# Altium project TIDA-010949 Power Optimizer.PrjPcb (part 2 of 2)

## Sheet TIDA-010949 Power Optimizer_Hardware.SchDoc
size 431 x 279 mm; Date: Not shown in title block; ApprovedBy: Not shown in title block; CheckedBy: Not shown in title block; Author: Not shown in title block; CompanyName: Not shown in title block; Engineer: Not shown in title block; Organization: Not shown in title block; Address1: Not shown in title block; Address2: Not shown in title block; Address3: Not shown in title block; Address4: Not shown in title block; DocumentNumber: 3; Revision: Use project parameter SCH_Rev; SheetNumber: 6; SheetTotal: 8; PageSetup: Record=PageOptions¦CenterHorizontal=True¦CenterVertical=True¦PrintScale=1.00¦XCorrection=1.00¦YCorrection=1.00¦PrintKind=0¦BorderSize=5000000¦LeftOffset=0¦BottomOffset=0¦Orientation=2¦PaperLength=1000¦PaperWidth=1000¦Scale=100¦PaperSource=15¦PrintQuality=600¦MediaType=1¦DitherType=10¦PaperKind=Letter¦PrintScaleMode=1
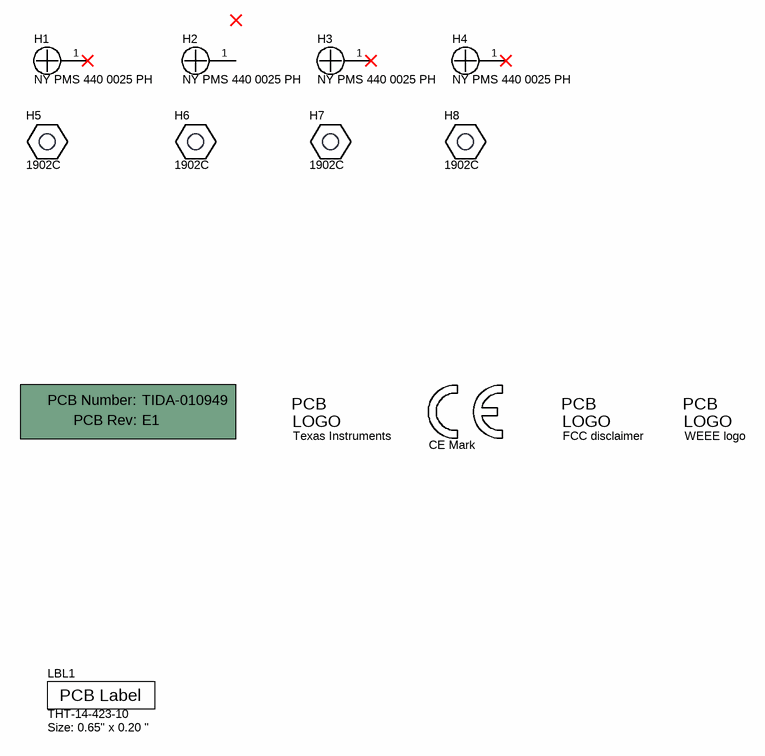
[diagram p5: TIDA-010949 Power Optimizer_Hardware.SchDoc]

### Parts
!PCB  Printed Circuit Board  (value not drawn)  (mechanical)
H1  NY PMS 440 0025 PH  [NY PMS 440 0025 PH]
H2  NY PMS 440 0025 PH  [NY PMS 440 0025 PH]
H3  NY PMS 440 0025 PH  [NY PMS 440 0025 PH]
H4  NY PMS 440 0025 PH  [NY PMS 440 0025 PH]
H5  1902C  [Keystone_1902C]
H6  1902C  [Keystone_1902C]
H7  1902C  [Keystone_1902C]
H8  1902C  [Keystone_1902C]
LBL1  THT-14-423-10  Note: Size: 0.65" x 0.20 "  [Label_650x200]
Logo1  Texas Instruments  [TI_Stacked_Overlay_Small]  (no BOM)
Logo2  CE Mark  [CE_Mark_5mm]  (no BOM)
Logo3  FCC disclaimer  [FCC_disclaimer]  (no BOM)
Logo4  WEEE logo  [WEEE_Minimum]  (no BOM)

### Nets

Not connected (* = marked no-connect by the designer): H1 1*; H2 1; H3 1*; H4 1*

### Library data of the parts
!PCB = CMP-0003618-2: Manufacturer: Any; PartNumber: TIDA-010949
H1-H4 = CMP-0003617-1: Machine Screw, Round, #4-40 x 1/4, Nylon, Philips panhead; Manufacturer: B&F Fastener Supply; CompType: Hardware
H5-H8 = CMP-0003610-1: Standoff, Hex, 0.5"L #4-40 Nylon; Manufacturer: Keystone; CompType: Hardware
LBL1 = CMP-0003625-1: Thermal Transfer Printable Labels, 0.650" W x 0.200" H - 10,000 per roll; Manufacturer: Brady; CompType: Label
Logo1 = CMP-0074838-1: Texas Instrument Corporate Signature; SymbolCreator: a0412235; Lib Reference: TI_Logo; Library Reference: Logo
Logo2 = CMP-0074844-1: SymbolCreator: a0412235
Logo3 = CMP-0074847-1: FCC_disclaimer; Library Reference: Logo
Logo4 = CMP-0074769-1

## Sheet TIDA-010949 Power Optimizer_Sampling.SchDoc
size A4; Date: Not shown in title block; ApprovedBy: Not shown in title block; CheckedBy: Not shown in title block; Author: Not shown in title block; CompanyName: Not shown in title block; Engineer: Not shown in title block; Organization: Not shown in title block; Address1: Not shown in title block; Address2: Not shown in title block; Address3: Not shown in title block; Address4: Not shown in title block; DocumentNumber: 1; Revision: Use project parameter SCH_Rev; SheetNumber: 8; SheetTotal: 8; PageSetup: Record=PageOptions¦CenterHorizontal=True¦CenterVertical=True¦PrintScale=0.93¦XCorrection=1.00¦YCorrection=1.00¦PrintKind=0¦BorderSize=5000000¦LeftOffset=0¦BottomOffset=0¦Orientation=2¦PaperLength=1000¦PaperWidth=1000¦Scale=100¦PaperSource=15¦PrintQuality=600¦MediaType=1¦DitherType=10¦PaperKind=Letter¦PrintScaleMode=1
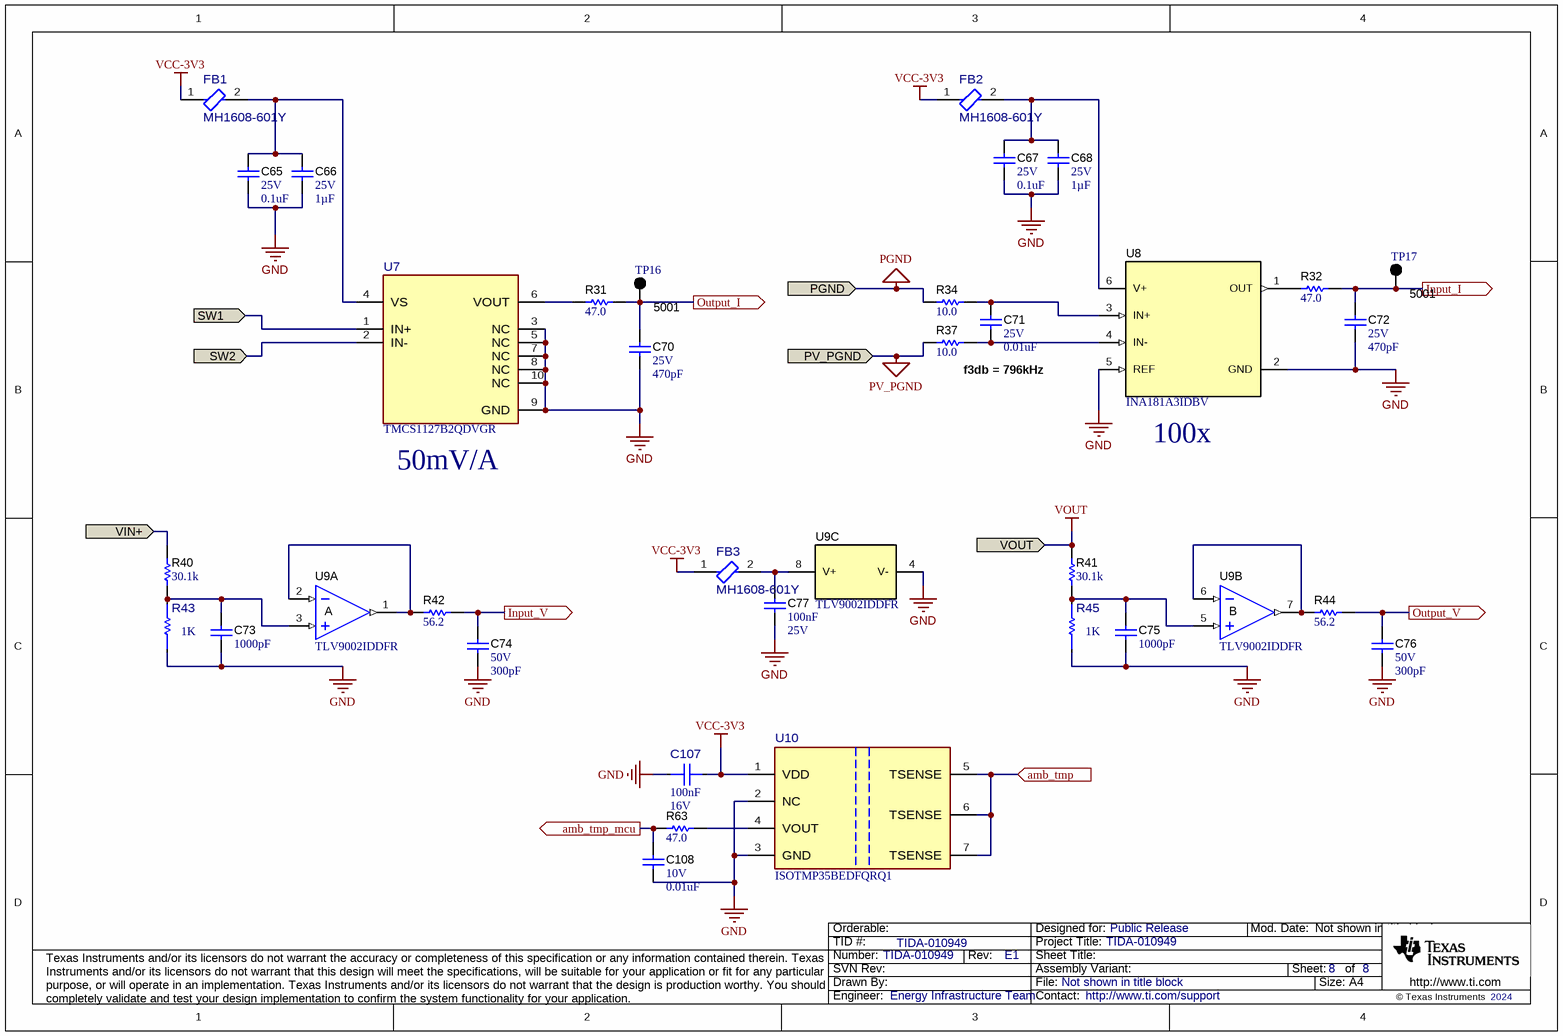
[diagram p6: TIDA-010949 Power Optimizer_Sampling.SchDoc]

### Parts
C65  VDC_V: 25V  ValueDisplayed: 0.1uF  [0402]  (hidden comment: GRM155R71E104KE14D)
C66  VDC_V: 25V  ValueDisplayed: 1µF  [0402]  (hidden comment: GRM155R61E105MA12D)
C67  VDC_V: 25V  ValueDisplayed: 0.1uF  [0402]  (hidden comment: GRM155R71E104KE14D)
C68  VDC_V: 25V  ValueDisplayed: 1µF  [0402]  (hidden comment: GRM155R61E105MA12D)
C70  VDC_V: 25V  ValueDisplayed: 470pF  [0402]  (hidden comment: GRM1555C1E471JA01D)
C71  VDC_V: 25V  ValueDisplayed: 0.01uF  [0402]  (hidden comment: GRM155R71E103KA01D)
C72  VDC_V: 25V  ValueDisplayed: 470pF  [0402]  (hidden comment: GRM1555C1E471JA01D)
C73  ValueDisplayed: 1000pF  [0603]  (hidden comment: CC0603JRNPO8BN102)
C74  VDC_V: 50V  ValueDisplayed: 300pF  [0402]  (hidden comment: GRM1555C1H301JA01D)
C75  ValueDisplayed: 1000pF  [0603]  (hidden comment: CC0603JRNPO8BN102)
C76  VDC_V: 50V  ValueDisplayed: 300pF  [0402]  (hidden comment: GRM1555C1H301JA01D)
C77  Cap_F: 100nF  VDC_V: 25V  [0603]  (hidden comment: 06033C104JAT2A)
C107  Cap_F: 100nF  VDC_V: 16V  [FP-GCJ188R71C104KA01D_0603-MFG]  (hidden comment: GCJ188R71C104KA01D)
C108  VDC_V: 10V  ValueDisplayed: 0.01uF  [0402]  (hidden comment: GRM155R61A103KA01D)
FB1  MH1608-601Y  [FP-MH1608-601Y_0603-MFG]
FB2  MH1608-601Y  [FP-MH1608-601Y_0603-MFG]
FB3  MH1608-601Y  [FP-MH1608-601Y_0603-MFG]
R31  ValueDisplayed: 47.0  [0402]  (hidden comment: RK73H1ETTP47R0F)
R32  ValueDisplayed: 47.0  [0402]  (hidden comment: RK73H1ETTP47R0F)
R34  ValueDisplayed: 10.0  [0402]  (hidden comment: RK73H1ETTP10R0F)
R37  ValueDisplayed: 10.0  [0402]  (hidden comment: RK73H1ETTP10R0F)
R40  ValueDisplayed: 30.1k  [0805_HV]  (hidden comment: RR1220P-3012-D-M)
R41  ValueDisplayed: 30.1k  [0805_HV]  (hidden comment: RR1220P-3012-D-M)
R42  ValueDisplayed: 56.2  [0402]  (hidden comment: CRCW040256R2FKED)
R43  value 1K  [FP-RT0603BRD071KL_0603-MFG]  (hidden comment: RT0603BRD071KL)
R44  ValueDisplayed: 56.2  [0402]  (hidden comment: CRCW040256R2FKED)
R45  value 1K  [FP-RT0603BRD071KL_0603-MFG]  (hidden comment: RT0603BRD071KL)
R63  ValueDisplayed: 47.0  [0402]  (hidden comment: RK73H1ETTP47R0F)
TP16  5001  [Keystone5001]
TP17  5001  [Keystone5001]
U7  TMCS1127B2QDVGR  [DVG0010A-MFG]
U8  INA181A3IDBV  [DBV0006A_N]
U9  TLV9002IDDFR  [DDF0008A_N]  (parts A,B,C of 3)
U10  ISOTMP35BEDFQRQ1  [DFQ0007A-MFG]

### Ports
amb_tmp (in), amb_tmp_mcu (out), Input_I (out), Input_V (out), Output_I (out), Output_V (out), PGND (in), PV_PGND (in), SW1 (in), SW2 (in), VIN+ (in), VOUT (in)

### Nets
GND: C65.2 C66.2 C67.2 C68.2 C70.2 C72.2 C73.2 C74.2 C75.2 C76.2 C77.1 C107.1 C108.2 R43.1 R45.1 U7.3(NC) U7.5(NC) U7.7(NC) U7.8(NC) U7.9(GND) U7.10(NC) U8.2(GND) U8.5(REF) U9.4(V-) U10.2(NC) U10.3(GND)
PGND: R34.1 ; port PGND
PV_PGND: R37.1 ; port PV_PGND
VCC-3V3: C107.2 FB1.1 FB2.1 FB3.1 U10.1(VDD)
VOUT: R41.2 ; port VOUT
amb_tmp: U10.5(TSENSE) U10.6(TSENSE) U10.7(TSENSE) ; port amb_tmp
amb_tmp_mcu: C108.1 R63.1 ; port amb_tmp_mcu
Input_I: C72.1 R32.2 TP17.1 ; port Input_I
Input_V: C74.1 R42.2 ; port Input_V
Output_I: C70.1 R31.2 TP16.1 ; port Output_I
Output_V: C76.1 R44.2 ; port Output_V
SW1: U7.1(IN+) ; port SW1
SW2: U7.2(IN-) ; port SW2
VIN+: R40.2 ; port VIN+
NetC65_1: C65.1 C66.1 FB1.2 U7.4(VS)
NetC67_1: C67.1 C68.1 FB2.2 U8.6(V+)
NetC71_1: C71.1 R34.2 U8.3(IN+)
NetC71_2: C71.2 R37.2 U8.4(IN-)
NetC73_1: C73.1 R40.1 R43.2 U9.3(IN+)
NetC75_1: C75.1 R41.1 R45.2 U9.5(IN+)
NetC77_2: C77.2 FB3.2 U9.8(V+)
NetR31_1: R31.1 U7.6(VOUT)
NetR32_1: R32.1 U8.1(OUT)
NetR42_1: R42.1 U9.1(OUT) U9.2(IN-)
NetR44_1: R44.1 U9.6(IN-) U9.7(OUT)
NetR63_2: R63.2 U10.4(VOUT)

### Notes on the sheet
- f3db = 796kHz
- (near U8) 100x
- (near U7) 50mV/A

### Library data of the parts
C65 C67 = CMP-0006659-2: CAP, CERM, 0.1 uF, 25 V, +/- 10%, X7R, 0402; Manufacturer: MuRata; TaMin_C: -55°C; Polarized: N; SizeAreaWB_mm2: 3; Value1: Unknown; U/M: EA; Value: 0.1uF; TaMax_C: 125°C; SizeZ_mm: 0.6; SizeX_mm: 1; SizeY_mm: 0.5; Cap_F: 100nF; AEC Category: Q200
C66 C68 = CMP-0078625-1: CAP, CERM, 1 µF, 25 V,+/- 20%, X5R, 0402; Manufacturer: MuRata; SizeAreaWB_mm2: 3; SizeArea_mm2: 0.5; AEC Qualified: N; AEC Category: Q200; Value: 1uF; TaMax_C: 85°C; SizeZ_mm: 0.6; TaMin_C: -55°C; U/M: EA; SizeX_mm: 1
C70 C72 = CMP-0006389-2: CAP, CERM, 470 pF, 25 V, +/- 5%, C0G/NP0, 0402; Manufacturer: MuRata; TaMin_C: -55°C; Polarized: N; SizeAreaWB_mm2: 3; Value1: Unknown; U/M: EA; Value: 470pF; TaMax_C: 125°C; SizeZ_mm: 0.6; SizeX_mm: 1; SizeY_mm: 0.5; AEC Category: Q200
C71 = CMP-0006658-2: CAP, CERM, 0.01 uF, 25 V, +/- 10%, X7R, 0402; Manufacturer: MuRata; TaMin_C: -55°C; Polarized: N; SizeAreaWB_mm2: 3; Value1: Unknown; U/M: EA; Value: 0.01uF; TaMax_C: 125°C; SizeZ_mm: 0.6; SizeX_mm: 1; SizeY_mm: 0.5; Cap_F: 10nF; AEC Category: Q200
C73 C75 = CMP-0860530-1: CAP, CERM, 1000 pF, 25 V,+/- 5%, C0G/NP0, 0603; Manufacturer: Yageo; SizeX_mm: 1.6; SizeArea_mm2: 1.28; Value: 1000pF; AEC Category: Q200; Cap_F: 1nF; Value2: 25V; Polarized: N; U/M: EA; SizeY_mm: 0.8; SizeZ_mm: 1; TaMax_C: 125°C; TaMin_C: -55°C; SizeAreaWB_mm2: 4.68
C74 C76 = CMP-0006453-2: CAP, CERM, 300 pF, 50 V, +/- 5%, C0G/NP0, 0402; Manufacturer: MuRata; TaMin_C: -55°C; Polarized: N; SizeAreaWB_mm2: 3; Value1: Unknown; U/M: EA; Value: 300pF; TaMax_C: 125°C; SizeZ_mm: 0.6; SizeX_mm: 1; SizeY_mm: 0.5; AEC Category: Q200
C77 = CMP-0006752-5: CAP, CERM, 0.1 uF, 25 V, +/- 5%, X7R, 0603; Manufacturer: AVX; TaMin_C: -55°C; ESR_ohm: 0.05; Polarized: N; SizeAreaWB_mm2: 4.68; Value1: 0.05 ohm; U/M: EA; Value: 0.1uF; TaMax_C: 125°C; SizeZ_mm: 1; SizeX_mm: 1.6; SizeY_mm: 0.8; SizeArea_mm2: 1.28; AEC Category: Q200
C107 = CMP-0090409-1: 0.1µF ±10% 16V Ceramic Capacitor X7R 0603 (1608 Metric); Manufacturer: Murata Electronics North America; AEC Grade: Grade 1; ValueDisplayed: 0.1uF; AEC Qualified: Yes; SizeZ_mm: 0.9mm; TempCo: 15%; Value: 100nF
C108 = CMP-0006561-2: CAP, CERM, 0.01 uF, 10 V, +/- 10%, X5R, 0402; Manufacturer: MuRata; TaMin_C: -55°C; Polarized: N; SizeAreaWB_mm2: 3; Value1: Unknown; U/M: EA; Value: 0.01uF; TaMax_C: 85°C; SizeZ_mm: 0.6; SizeX_mm: 1; SizeY_mm: 0.5; Cap_F: 10nF; AEC Category: Q200
FB1-FB3 = CMP-0037505-1: 600 Ohms @ 100 MHz 1 Power, Signal Line Ferrite Bead 0603 (1608 Metric) 1A 200mOhm; Manufacturer: Bourns; DCR_ohm: 0.2; SizeZ_mm: 1mm; AEC Qualified: No; Impedance At Frequency: 600Ω @ 100MHz; Test Frequency: 100MHz; Tolerance_%: 25%
R31 R32 R63 = CMP-0026751-1: RES, 47.0, 1%, 0.063 W, 0402; Manufacturer: KOA Speer; Power_W: 63mW; TempCo: 100 ppm/C; Value_Code: 47R0; U/M: EA; Value: 47.0; Res_ohm: 47; SizeX_mm: 1; SizeY_mm: 0.5; SizeZ_mm: 0.6; Value2: 0.063W; AEC Qualified: N; VDC_V: 50V; AEC Category: Q200
R34 R37 = CMP-0026749-1: RES, 10.0, 1%, 0.063 W, 0402; Manufacturer: KOA Speer; Power_W: 63mW; TempCo: 100 ppm/C; Value_Code: 10R0; U/M: EA; Value: 10.0; EIA_Code: E96; Res_ohm: 10; SizeX_mm: 1; SizeY_mm: 0.5; SizeZ_mm: 0.6; Value2: 0.063W; AEC Qualified: N; VDC_V: 50V; AEC Category: Q200
R40 R41 = CMP-0019234-2: RES, 30.1 k, 0.5%, 0.1 W, 0805; Manufacturer: Susumu Co Ltd; Power_W: 100mW; TempCo: 25 ppm/C; Value_Code: 30k1; U/M: EA; Value: 30.1k; EIA_Code: E192; SizeX_mm: 2; SizeY_mm: 1.25; SizeZ_mm: 1.45; Value2: 0.1W; SizeArea_mm2: 2.5; VDC_V: 100V; AEC Category: Q200
R42 R44 = CMP-0026454-2: RES, 56.2, 1%, 0.063 W, AEC-Q200 Grade 0, 0402; Manufacturer: Vishay-Dale; Power_W: 63mW; TempCo: 100 ppm/C; Value_Code: 56R2; Value: 56.2; EIA_Code: E96; SizeX_mm: 1; SizeY_mm: 0.5; SizeZ_mm: 0.6; Value2: 0.063W; AEC Qualified: Y; VDC_V: 50V; AEC Category: Q200; AEC Grade: 0
R43 R45 = CMP-0088560-2: High Precision-High Stability Chip Resistor Thin Film 0603 1kOhm 0.1% Paper T/R; Manufacturer: Yageo; SizeZ_mm: 0.55mm; TempCo: 25ppm/°C; Power_W: 100mW; AEC Qualified: No; VDC_V: 75V
TP16 TP17 = CMP-0055138-2: Test Point, Miniature, Black, TH; Manufacturer: Keystone Electronics; ContactFinish: Silver; CNHeader: FALSE; Green_Lifecycle: Active; Green_REACh: Passed; CT: TRUE
U7 = CMP-0097970-1: Manufacturer: Texas Instruments; Standoff Height: 0.1mm; SizeZ_mm: 2.65mm
U8 = CMP-0013234-2: Bidirectional, Low- and High-Side Measurement, Multichannel, Voltage Output, Current-Sense Amplifier, DBV0006A (SOT-6); Manufacturer: Texas Instruments; SizeX_mm: 2.8; SizeY_mm: 2.9; CompType: IC; SizeZ_mm: 1.45; SizeArea_mm2: 8.12; SizeAreaWB_mm2: 14.82; U/M: EA
U9 = CMP-0086102-1: TLV9002IDDFR, DDF0008A (SOT-23-THN-8); Manufacturer: Texas Instruments; SizeY_mm: 2.9; CompType: IC; SizeX_mm: 2.8; AEC Category: Q200; SizeAreaWB_mm2: 14.82; AEC Qualified: N; SizeArea_mm2: 8.12; SizeZ_mm: 1.1
U10 = CMP-0122473-1: Automotive ±1.5°C, 3-kVRMS Isolated Temperature Sensor With Analog Output With < 2 Seconds Response Time and 500VRMS Working Voltage; Manufacturer: Texas Instruments; SizeZ_mm: 1.75mm; AEC Qualified: Yes; AEC Grade: Grade 0; Max Supply Voltage: 5.5V; Min Supply Voltage: 2.3V; Operating Supply Current: 10uA; Sensor Output: Analog Voltage; Standoff Height: 0.11mm; TaMax_C: +150°C; TaMin_C: -40°C; TJmax_C: +155°C

## Sheet TIDA-010949 Power Optimizer_power stage.SchDoc
size 431 x 279 mm; Date: Not shown in title block; ApprovedBy: Not shown in title block; CheckedBy: Not shown in title block; Author: Not shown in title block; CompanyName: Not shown in title block; Engineer: Not shown in title block; Organization: Not shown in title block; Address1: Not shown in title block; Address2: Not shown in title block; Address3: Not shown in title block; Address4: Not shown in title block; DocumentNumber: 1; Revision: Use project parameter SCH_Rev; SheetNumber: 2; SheetTotal: 8; PageSetup: Record=PageOptions¦CenterHorizontal=True¦CenterVertical=True¦PrintScale=1.00¦XCorrection=1.00¦YCorrection=1.00¦PrintKind=0¦BorderSize=5000000¦LeftOffset=0¦BottomOffset=0¦Orientation=2¦PaperLength=1000¦PaperWidth=1000¦Scale=100¦PaperSource=15¦PrintQuality=600¦MediaType=1¦DitherType=10¦PaperKind=Letter¦PrintScaleMode=1
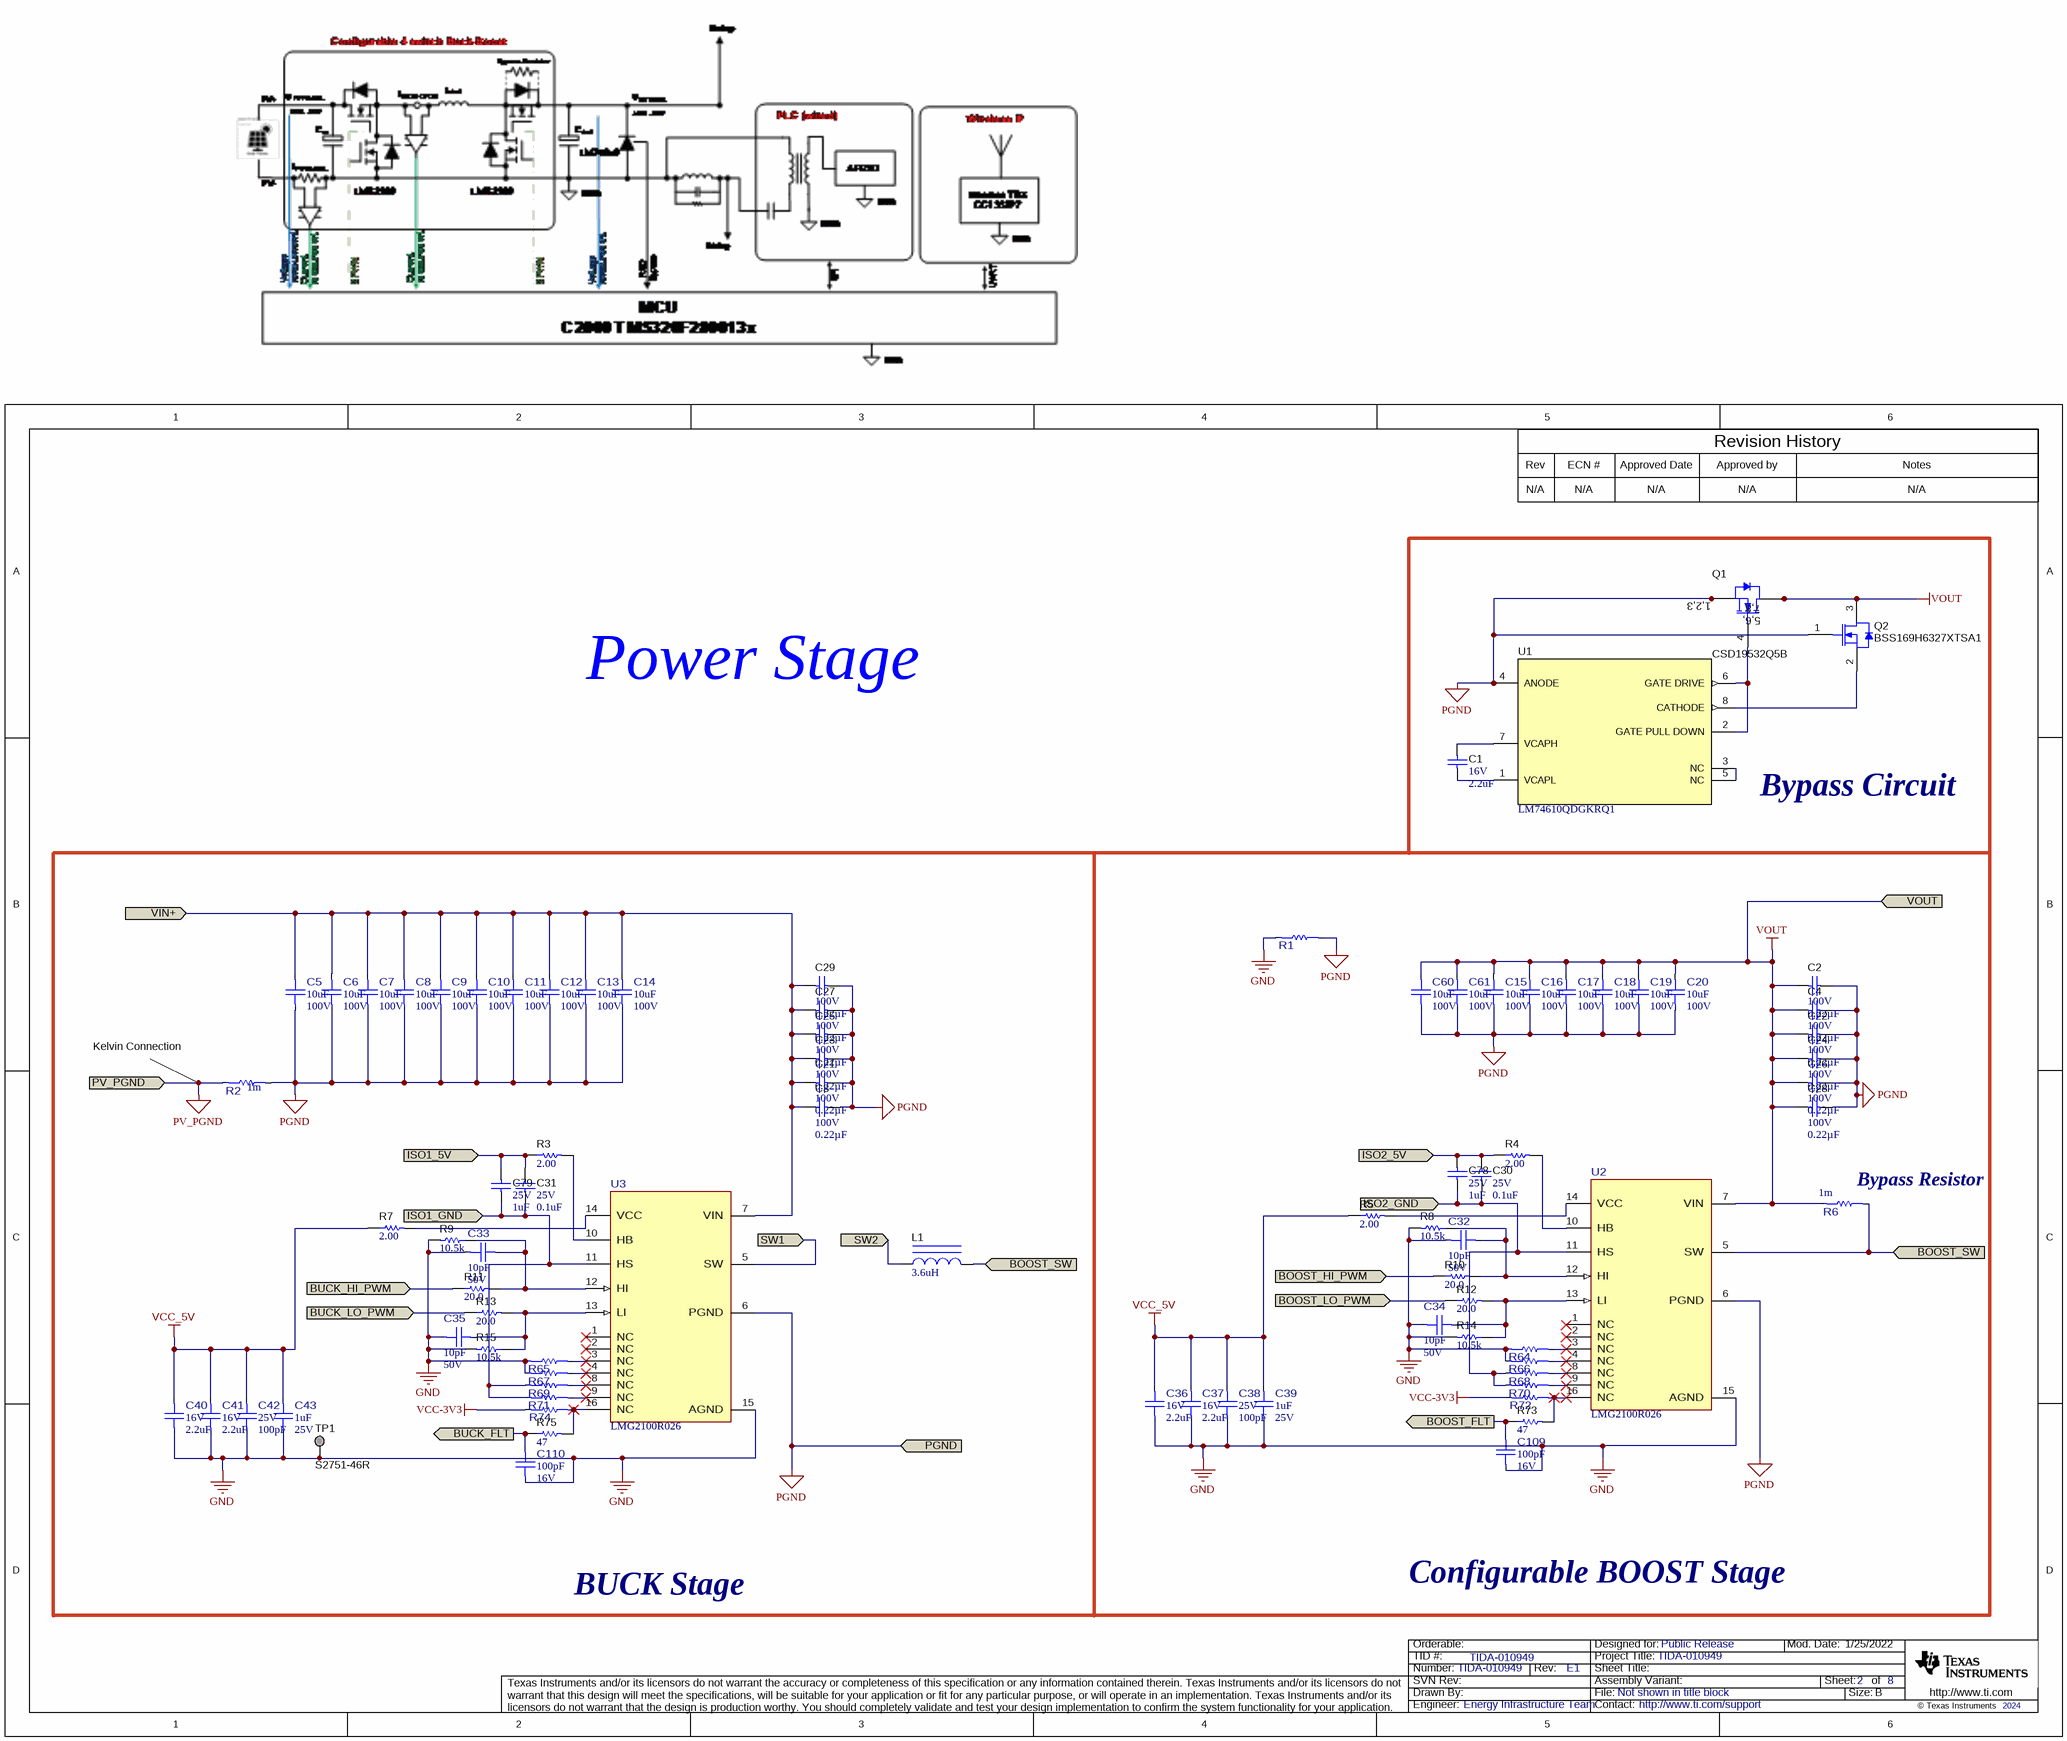
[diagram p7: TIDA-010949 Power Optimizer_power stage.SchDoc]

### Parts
C1  VDC_V: 16V  ValueDisplayed: 2.2uF  [0805_HV]  (hidden comment: 0805YD225KAT2A)
C2  VDC_V: 100V  ValueDisplayed: 0.22µF  [0603]  (hidden comment: HMK107C7224KAHTE)
C3  VDC_V: 100V  ValueDisplayed: 0.22µF  [0603]  (hidden comment: HMK107C7224KAHTE)
C4  VDC_V: 100V  ValueDisplayed: 0.22µF  [0603]  (hidden comment: HMK107C7224KAHTE)
C5  ValueDisplayed: 10uF  VDC_V: 100V  [FP-GRM32EC72A106KE05L_1210-MFG]  (hidden comment: GRM32EC72A106KE05L)
C6  ValueDisplayed: 10uF  VDC_V: 100V  [FP-GRM32EC72A106KE05L_1210-MFG]  (hidden comment: GRM32EC72A106KE05L)
C7  ValueDisplayed: 10uF  VDC_V: 100V  [FP-GRM32EC72A106KE05L_1210-MFG]  (hidden comment: GRM32EC72A106KE05L)
C8  ValueDisplayed: 10uF  VDC_V: 100V  [FP-GRM32EC72A106KE05L_1210-MFG]  (hidden comment: GRM32EC72A106KE05L)
C9  ValueDisplayed: 10uF  VDC_V: 100V  [FP-GRM32EC72A106KE05L_1210-MFG]  (hidden comment: GRM32EC72A106KE05L)
C10  ValueDisplayed: 10uF  VDC_V: 100V  [FP-GRM32EC72A106KE05L_1210-MFG]  (hidden comment: GRM32EC72A106KE05L)
C11  ValueDisplayed: 10uF  VDC_V: 100V  [FP-GRM32EC72A106KE05L_1210-MFG]  (hidden comment: GRM32EC72A106KE05L)
C12  ValueDisplayed: 10uF  VDC_V: 100V  [FP-GRM32EC72A106KE05L_1210-MFG]  (hidden comment: GRM32EC72A106KE05L)
C13  ValueDisplayed: 10uF  VDC_V: 100V  [FP-GRM32EC72A106KE05L_1210-MFG]  (hidden comment: GRM32EC72A106KE05L)
C14  ValueDisplayed: 10uF  VDC_V: 100V  [FP-GRM32EC72A106KE05L_1210-MFG]  (hidden comment: GRM32EC72A106KE05L)
C15  ValueDisplayed: 10uF  VDC_V: 100V  [FP-GRM32EC72A106KE05L_1210-MFG]  (hidden comment: GRM32EC72A106KE05L)
C16  ValueDisplayed: 10uF  VDC_V: 100V  [FP-GRM32EC72A106KE05L_1210-MFG]  (hidden comment: GRM32EC72A106KE05L)
C17  ValueDisplayed: 10uF  VDC_V: 100V  [FP-GRM32EC72A106KE05L_1210-MFG]  (hidden comment: GRM32EC72A106KE05L)
C18  ValueDisplayed: 10uF  VDC_V: 100V  [FP-GRM32EC72A106KE05L_1210-MFG]  (hidden comment: GRM32EC72A106KE05L)
C19  ValueDisplayed: 10uF  VDC_V: 100V  [FP-GRM32EC72A106KE05L_1210-MFG]  (hidden comment: GRM32EC72A106KE05L)
C20  ValueDisplayed: 10uF  VDC_V: 100V  [FP-GRM32EC72A106KE05L_1210-MFG]  (hidden comment: GRM32EC72A106KE05L)
C21  VDC_V: 100V  ValueDisplayed: 0.22µF  [0603]  (hidden comment: HMK107C7224KAHTE)
C22  VDC_V: 100V  ValueDisplayed: 0.22µF  [0603]  (hidden comment: HMK107C7224KAHTE)
C23  VDC_V: 100V  ValueDisplayed: 0.22µF  [0603]  (hidden comment: HMK107C7224KAHTE)
C24  VDC_V: 100V  ValueDisplayed: 0.22µF  [0603]  (hidden comment: HMK107C7224KAHTE)
C25  VDC_V: 100V  ValueDisplayed: 0.22µF  [0603]  (hidden comment: HMK107C7224KAHTE)
C26  VDC_V: 100V  ValueDisplayed: 0.22µF  [0603]  (hidden comment: HMK107C7224KAHTE)
C27  VDC_V: 100V  ValueDisplayed: 0.22µF  [0603]  (hidden comment: HMK107C7224KAHTE)
C28  VDC_V: 100V  ValueDisplayed: 0.22µF  [0603]  (hidden comment: HMK107C7224KAHTE)
C29  VDC_V: 100V  ValueDisplayed: 0.22µF  [0603]  (hidden comment: HMK107C7224KAHTE)
C30  VDC_V: 25V  ValueDisplayed: 0.1uF  [0402S]  (hidden comment: GRM155R71E104KE14D)
C31  VDC_V: 25V  ValueDisplayed: 0.1uF  [0402S]  (hidden comment: GRM155R71E104KE14D)
C32  ValueDisplayed: 10pF  VDC_V: 50V  [FP-04025U100FAT2A_0402-MFG]  (hidden comment: 04025U100FAT2A)
C33  ValueDisplayed: 10pF  VDC_V: 50V  [FP-04025U100FAT2A_0402-MFG]  (hidden comment: 04025U100FAT2A)
C34  ValueDisplayed: 10pF  VDC_V: 50V  [FP-04025U100FAT2A_0402-MFG]  (hidden comment: 04025U100FAT2A)
C35  ValueDisplayed: 10pF  VDC_V: 50V  [FP-04025U100FAT2A_0402-MFG]  (hidden comment: 04025U100FAT2A)
C36  VDC_V: 16V  ValueDisplayed: 2.2uF  [FP-GRM188C71C225KE11D_0603-MFG]  (hidden comment: GRM188C71C225KE11D)
C37  VDC_V: 16V  ValueDisplayed: 2.2uF  [FP-GRM188C71C225KE11D_0603-MFG]  (hidden comment: GRM188C71C225KE11D)
C38  VDC_V: 25V  ValueDisplayed: 100pF  [FP-GRT1555C1E101JA02D_0402-MFG]  (hidden comment: GRT1555C1E101JA02D)
C39  ValueDisplayed: 1uF  VDC_V: 25V  [FP-GRT155R61E105KE01D_0402-MFG]  (hidden comment: GRT155R61E105KE01D)
C40  VDC_V: 16V  ValueDisplayed: 2.2uF  [FP-GRM188C71C225KE11D_0603-MFG]  (hidden comment: GRM188C71C225KE11D)
C41  VDC_V: 16V  ValueDisplayed: 2.2uF  [FP-GRM188C71C225KE11D_0603-MFG]  (hidden comment: GRM188C71C225KE11D)
C42  VDC_V: 25V  ValueDisplayed: 100pF  [FP-GRT1555C1E101JA02D_0402-MFG]  (hidden comment: GRT1555C1E101JA02D)
C43  ValueDisplayed: 1uF  VDC_V: 25V  [FP-GRT155R61E105KE01D_0402-MFG]  (hidden comment: GRT155R61E105KE01D)
C60  ValueDisplayed: 10uF  VDC_V: 100V  [FP-GRM32EC72A106KE05L_1210-MFG]  (hidden comment: GRM32EC72A106KE05L)
C61  ValueDisplayed: 10uF  VDC_V: 100V  [FP-GRM32EC72A106KE05L_1210-MFG]  (hidden comment: GRM32EC72A106KE05L)
C78  VDC_V: 25V  ValueDisplayed: 1uF  [0402S]  (hidden comment: GRM155R61E105KA12D)
C79  VDC_V: 25V  ValueDisplayed: 1uF  [0402S]  (hidden comment: GRM155R61E105KA12D)
C109  ValueDisplayed: 100pF  VDC_V: 16V  [FP-C0402C101J4GAC7867_0402-MFG]  (hidden comment: C0402C101J4GAC7867)
C110  ValueDisplayed: 100pF  VDC_V: 16V  [FP-C0402C101J4GAC7867_0402-MFG]  (hidden comment: C0402C101J4GAC7867)
L1  ValueDisplayed: 3.6uH  [SER2013]  (hidden comment: SER2013-362MLB)
Q1  CSD19532Q5B  [DNK0008A]
Q2  BSS169H6327XTSA1  [SOT-23]
R1  CR0402-10W-000T  [FP-CR0402-10W-000T_0402-MFG]  (value not drawn)
R2  value 1m  [FP-ULRG32512R001FLFSLT_2512-MFG]  (hidden comment: ULRG32512R001FLFSLT)
R3  ValueDisplayed: 2.00  [0402S]  (hidden comment: CRCW04022R00FKED)
R4  ValueDisplayed: 2.00  [0402S]  (hidden comment: CRCW04022R00FKED)
R5  ValueDisplayed: 2.00  [0402S]  (hidden comment: CRCW04022R00FKED)
R6  value 1m  [FP-ULRG32512R001FLFSLT_2512-MFG]  (hidden comment: ULRG32512R001FLFSLT)
R7  ValueDisplayed: 2.00  [0402S]  (hidden comment: CRCW04022R00FKED)
R8  ValueDisplayed: 10.5k  [0402S]  (hidden comment: RC0402FR-0710K5L)
R9  ValueDisplayed: 10.5k  [0402S]  (hidden comment: RC0402FR-0710K5L)
R10  ValueDisplayed: 20.0  [0603]  (hidden comment: RC0603FR-0720RL)
R11  ValueDisplayed: 20.0  [0603]  (hidden comment: RC0603FR-0720RL)
R12  ValueDisplayed: 20.0  [0603]  (hidden comment: RC0603FR-0720RL)
R13  ValueDisplayed: 20.0  [0603]  (hidden comment: RC0603FR-0720RL)
R14  ValueDisplayed: 10.5k  [0402S]  (hidden comment: RC0402FR-0710K5L)
R15  ValueDisplayed: 10.5k  [0402S]  (hidden comment: RC0402FR-0710K5L)
R64  D1LPC0402CJUMPF-T10  [FP-D1LPC0402CJUMPF-T10_0402-MFG]  (value not drawn)
R65  D1LPC0402CJUMPF-T10  [FP-D1LPC0402CJUMPF-T10_0402-MFG]  (value not drawn)
R66  D1LPC0402CJUMPF-T10  [FP-D1LPC0402CJUMPF-T10_0402-MFG]  (value not drawn)
R67  D1LPC0402CJUMPF-T10  [FP-D1LPC0402CJUMPF-T10_0402-MFG]  (value not drawn)
R68  D1LPC0402CJUMPF-T10  [FP-D1LPC0402CJUMPF-T10_0402-MFG]  (value not drawn)
R69  D1LPC0402CJUMPF-T10  [FP-D1LPC0402CJUMPF-T10_0402-MFG]  (value not drawn)
R70  D1LPC0402CJUMPF-T10  [FP-D1LPC0402CJUMPF-T10_0402-MFG]  (value not drawn)
R71  D1LPC0402CJUMPF-T10  [FP-D1LPC0402CJUMPF-T10_0402-MFG]  (value not drawn)
R72  ERJ-H2GJ472X  [FP-ERJ-H2GJ472X_0402-MFG]  (value not drawn)
R73  ValueDisplayed: 47  [0402S]  (hidden comment: CRCW040247R0JNED)
R74  ERJ-H2GJ472X  [FP-ERJ-H2GJ472X_0402-MFG]  (value not drawn)
R75  ValueDisplayed: 47  [0402S]  (hidden comment: CRCW040247R0JNED)
TP1  S2751-46R  [Harwin_S2751-46R]  (no BOM)
U1  LM74610QDGKRQ1  [DGK0008A_N]
U2  LMG2100R026  [VBN0016A-MFG]
U3  LMG2100R026  [VBN0016A-MFG]

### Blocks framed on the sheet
Bypass Circuit: C1 Q1 Q2 U1
BUCK Stage: C3 C5-C14 C21 C23 C25 C27 C29 C31 C33 C35 C40-C43 C79 C110 L1 R2 R3 R7 R9 R11 R13 R15 R65 R67 R69 R71 R74 R75 TP1 U3
Configurable BOOST Stage: C2 C4 C15-C20 C22 C24 C26 C28 C30 C32 C34 C36-C39 C60 C61 C78 C109 R1 R4-R6 R8 R10 R12 R14 R64 R66 R68 R70 R72 R73 U2

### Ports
BOOST_FLT (out), BOOST_HI_PWM (in), BOOST_LO_PWM (in), BOOST_SW (in), BUCK_FLT (out), BUCK_HI_PWM (in), BUCK_LO_PWM (in), ISO1_5V (in), ISO1_GND (in), ISO2_5V (in), ISO2_GND (in), PGND (in), PV_PGND (in), SW1 (in), SW2 (in), VIN+ (in), VOUT (in)

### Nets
GND: C32.1 C33.1 C34.1 C35.1 C36.1 C37.1 C38.1 C39.1 C40.1 C41.1 C42.1 C43.1 C109.1 C110.1 R1.1 R8.2 R9.2 R14.2 R15.2 R64.1 R65.1 R66.1 R67.1 TP1.1 U2.15(AGND) U3.15(AGND)
PGND: C2.1 C3.1 C4.1 C5.1 C6.1 C7.1 C8.1 C9.1 C10.1 C11.1 C12.1 C13.1 C14.1 C15.1 C16.1 C17.1 C18.1 C19.1 C20.1 C21.1 C22.1 C23.1 C24.1 C25.1 C26.1 C27.1 C28.1 C29.1 C60.1 C61.1 Q1.1(S) Q1.2(S) Q1.3(S) Q2.1(G) R1.2 R2.2 U1.4(ANODE) U2.6(PGND) U3.6(PGND) ; port PGND
PV_PGND: R2.1 ; port PV_PGND
VCC-3V3: R72.2 R74.2
VCC_5V: C36.2 C37.2 C38.2 C39.2 C40.2 C41.2 C42.2 C43.2 R5.1 R7.1
VOUT: C2.2 C4.2 C15.2 C16.2 C17.2 C18.2 C19.2 C20.2 C22.2 C24.2 C26.2 C28.2 C60.2 C61.2 Q1.5(D) Q1.6(D) Q1.7(D) Q1.8(D) Q1.9(D) Q2.3(D) R6.1 U2.7(VIN) ; port VOUT
BOOST_FLT: C109.2 R73.1 ; port BOOST_FLT
BOOST_HI_PWM: R10.1 ; port BOOST_HI_PWM
BOOST_LO_PWM: R12.1 ; port BOOST_LO_PWM
BOOST_SW: L1.2 R6.2 U2.5(SW) ; port BOOST_SW
BUCK_FLT: C110.2 R75.1 ; port BUCK_FLT
BUCK_HI_PWM: R11.1 ; port BUCK_HI_PWM
BUCK_LO_PWM: R13.1 ; port BUCK_LO_PWM
ISO1_5V: C31.1 C79.1 R3.1 ; port ISO1_5V
ISO1_GND: C31.2 C79.2 R69.1 R71.1 U3.11(HS) ; port ISO1_GND
ISO2_5V: C30.1 C78.1 R4.1 ; port ISO2_5V
ISO2_GND: C30.2 C78.2 R68.1 R70.1 U2.11(HS) ; port ISO2_GND
SW1: U3.5(SW) ; port SW1
SW2: L1.1 ; port SW2
VIN+: C3.2 C5.2 C6.2 C7.2 C8.2 C9.2 C10.2 C11.2 C12.2 C13.2 C14.2 C21.2 C23.2 C25.2 C27.2 C29.2 U3.7(VIN) ; port VIN+
NetC1_1: C1.1 U1.7(VCAPH)
NetC1_2: C1.2 U1.1(VCAPL)
NetC32_2: C32.2 R8.1 R10.2 U2.12(HI)
NetC33_2: C33.2 R9.1 R11.2 U3.12(HI)
NetC34_2: C34.2 R12.2 R14.1 U2.13(LI)
NetC35_2: C35.2 R13.2 R15.1 U3.13(LI)
NetQ1_4: Q1.4(G) U1.2(GATE_PULL_DOWN) U1.6(GATE_DRIVE)
NetQ2_2: Q2.2(S) U1.8(CATHODE)
NetR3_2: R3.2 U3.10(HB)
NetR4_2: R4.2 U2.10(HB)
NetR5_2: R5.2 U2.14(VCC)
NetR7_2: R7.2 U3.14(VCC)
NetR64_2: R64.2 U2.3(NC)
NetR65_2: R65.2 U3.3(NC)
NetR66_2: R66.2 U2.4(NC)
NetR67_2: R67.2 U3.4(NC)
NetR68_2: R68.2 U2.8(NC)
NetR69_2: R69.2 U3.8(NC)
NetR70_2: R70.2 U2.9(NC)
NetR71_2: R71.2 U3.9(NC)
NetR72_1: R72.1 R73.2 U2.16(NC)
NetR74_1: R74.1 R75.2 U3.16(NC)
NetU1_3: U1.3(NC) U1.5(NC)

Not connected (* = marked no-connect by the designer): U2 1(NC)* 2(NC)*; U3 1(NC)* 2(NC)*

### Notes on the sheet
- Rev
- N/A
- ECN #
- Approved Date
- Approved by
- Revision History
- Notes
- Power Stage
- Kelvin Connection
- (near R6) Bypass Resistor

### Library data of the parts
C1 = CMP-0007679-2: CAP, CERM, 2.2 uF, 16 V, +/- 10%, X5R, 0805; Manufacturer: AVX; TaMin_C: -55°C; ESR_ohm: 9m; Polarized: N; SizeAreaWB_mm2: 6.75; Value1: 0.009 ohm; U/M: EA; Value: 2.2uF; TaMax_C: 85°C; SizeZ_mm: 1.45; SizeX_mm: 2; SizeY_mm: 1.25; Cap_Case: 0805; SizeArea_mm2: 2.5; Cap_F: 2.2µF; AEC Category: Q200
C2-C4 C21-C29 = CMP-0077894-3: CAP, CERM, 0.22 µF, 100 V,+/- 10%, X7S, AEC-Q200 Grade 1, 0603; Manufacturer: Taiyo Yuden; TaMin_C: -55°C; Polarized: N; SizeAreaWB_mm2: 4.68; U/M: EA; Value: 0.22uF; TaMax_C: 125°C; SizeZ_mm: 1.0; SizeX_mm: 1.6; SizeY_mm: 0.8; SizeArea_mm2: 1.28; AEC Qualified: Y; Cap_F: 220nF; AEC Grade: 1; AEC Category: Q200
C5-C20 C60 C61 = CMP-0087970-1: 10µF ±10% 100V Ceramic Capacitor X7S 1210 (3225 Metric); Manufacturer: Murata; Symbol Name: SYM-GRM32EC72A106KE05L; Tolerance_%: 0.1; AEC Qualified: No; TempCo: 22%; SizeZ_mm: 2.7mm
C30 C31 = CMP-0006659-2: CAP, CERM, 0.1 uF, 25 V, +/- 10%, X7R, 0402; Manufacturer: MuRata; TaMin_C: -55°C; Polarized: N; SizeAreaWB_mm2: 3; Value1: Unknown; U/M: EA; Value: 0.1uF; TaMax_C: 125°C; SizeZ_mm: 0.6; SizeX_mm: 1; SizeY_mm: 0.5; Cap_Case: 0402; Cap_F: 100nF; AEC Category: Q200
C32-C35 = CMP-0097874-1: 10 pF ±1% 50V Ceramic Capacitor C0G, NP0 0402 (1005 Metric); Manufacturer: KYOCERA AVX; TempCo: 30ppm/°C; AEC Qualified: No; Value: 10pF; SizeZ_mm: 0.6mm
C36 C37 C40 C41 = CMP-0089452-2: 2.2µF ±10% 16V Ceramic Capacitor X7S 0603 (1608 Metric); Manufacturer: Murata; SizeZ_mm: 1mm; Value: 2.2uF; AEC Qualified: No; TempCo: 22%
C38 C42 = CMP-0096845-1: Multi-Layer Ceramic Capacitor 100pF 25V C0G ±5% 0402 Paper T/R; Manufacturer: Murata; AEC Qualified: Yes; AEC Grade: Grade 1; TempCo: 30ppm/°C; SizeZ_mm: 0.55mm
C39 C43 = CMP-0096975-1: Multi-Layer Ceramic Capacitor 1uF 25V X5R ±10% 0402 Paper T/R; Manufacturer: Murata; SizeZ_mm: 0.55mm; Value: 1µF; AEC Grade: Grade 3; AEC Qualified: Yes; TempCo: 0.15
C78 C79 = CMP-0006608-2: CAP, CERM, 1 uF, 25 V, +/- 10%, X5R, 0402; Manufacturer: MuRata; TaMin_C: -55°C; Polarized: N; SizeAreaWB_mm2: 3; Value1: Unknown; U/M: EA; Value: 1uF; TaMax_C: 85°C; SizeZ_mm: 0.6; SizeX_mm: 1; SizeY_mm: 0.5; Cap_Case: 0402; Cap_F: 1µF; AEC Category: Q200
C109 C110 = CMP-0098338-1: 100 pF ±5% 16V Ceramic Capacitor C0G, NP0 0402 (1005 Metric); Manufacturer: KEMET; AEC Qualified: No; SizeZ_mm: 0.55mm; TempCo: 30ppm/°C; Value: 100pF
L1 = CMP-0060824-1: Inductor, Shielded E Core, Ferrite, 3.6 uH, 25 A, 0.0017 ohm, SMD; Manufacturer: Coilcraft; Isat: 25A @ 10% inductance drop; Irms: 30A @ 40C rise; Green_Lifecycle: Not Set; SizeAreaWB_mm2: 438.426; DCR_ohm: 1.7m; Green_REACh: Incomplete; Value: 3.6uH; Imax_A: 25A; SizeZ_mm: 12.95; SizeX_mm: 19.18; SizeY_mm: 18.7; SizeArea_mm2: 358.666; Ind_H: 3.6µH; AEC Category: Q200
Q1 = CMP-0000958-3: MOSFET, N-CH, 100 V, 17 A, DNK0008A (VSON-CLIP-8); Alternate Manufacturer: None; Manufacturer: Texas Instruments; SizeZ_mm: 1; ChType: N; Value2: 48 nC; VdsMax_V: 100V; SizeX_mm: 6; SizeY_mm: 5; Vgs_V: 20V; QgTyp_nC: 48; Value: 100V; SizeArea_mm2: 30; AEC Category: Q101; IdsMax_A: 17A; SizeAreaWB_mm2: 56; U/M: EA
Q2 = CMP-0000949-3: MOSFET, N-CH, Depletion Mode, 100 V, 0.17 A, AEC-Q101, SOT-23; Alternate Manufacturer: None; Manufacturer: Infineon Technologies; SizeZ_mm: 1.1; ChType: N; Value2: 2.1 nC; VdsMax_V: 100V; SizeX_mm: 2.5; SizeY_mm: 3; Vgs_V: 20V; QgTyp_nC: 2.1; AEC Qualified: Y; Value: 100V; SizeArea_mm2: 7.5; AEC Category: Q101; IdsMax_A: 170mA; SizeAreaWB_mm2: 14
R1 = CMP-0094948-1: 0 Ohms Jumper 0.1W, 1/10W Chip Resistor 0402 (1005 Metric) - Thick Film; Manufacturer: Venkel; AEC Qualified: No; Value: 0uΩ; VDC_V: 50V; SizeZ_mm: 0.4mm; Res_ohm: 0; Power_W: 100mW
R2 R6 = CMP-0042666-1: Res Metal Strip 2512 0.001 Ohm 1% 3W ±50ppm/C Pad SMD Automotive T/R; Manufacturer: TT Electronics; AEC Grade: Grade 0; AEC Qualified: Yes; SizeZ_mm: 0.8mm; TempCo: 50ppm/°C; TaMax_C: +170°C; TaMin_C: -55°C
R3-R5 R7 = CMP-0026262-2: RES, 2.00, 1%, 0.063 W, AEC-Q200 Grade 0, 0402; Manufacturer: Vishay-Dale; Power_W: 63mW; TempCo: 100 ppm/C; Value_Code: 2R00; Value: 2.00; EIA_Code: E96; Res_ohm: 2; SizeX_mm: 1; SizeY_mm: 0.5; SizeZ_mm: 0.6; Value2: 0.063W; AEC Qualified: Y; VDC_V: 50V; AEC Category: Q200; AEC Grade: 0
R8 R9 R14 R15 = CMP-0078781-1: RES, 10.5 k, 1%, 0.063 W, 0402; Manufacturer: Yageo America; Value_Code: 10k5; SizeArea_mm2: 0.5; AEC Qualified: N; AEC Category: Q200; Value: 10.5k; SizeZ_mm: 0.6; EIA_Code: E96; TempCo: 100 ppm/C; Power_W: 63mW; VDC_V: 50V; Value2: 0.063W; SizeX_mm: 1
R10-R13 = CMP-0022908-4: RES, 20.0, 1%, 0.1 W, 0603; Manufacturer: Yageo; Power_W: 100mW; TempCo: 100 ppm/C; Value_Code: 20R0; Value: 20.0; EIA_Code: E96; Res_ohm: 20; SizeX_mm: 1.6; SizeY_mm: 0.8; SizeZ_mm: 1; Value2: 0.1W; SizeArea_mm2: 1.28; AEC Qualified: N; VDC_V: 75V; AEC Category: Q200; SizeAreaWB_mm2: 4.68
R64-R71 = CMP-0031873-1: 0 Ohms Jumper Chip Resistor 0402 (1005 Metric) Anti-Sulfur, Current Sense, Flame Retardant Coating, Moisture Resistant, Safety Metal Foil; Manufacturer: Thin Film Technology; AEC Qualified: No; Res_ohm: 0; SizeZ_mm: 0.45mm; Max Current: 20A; Value: 0
R72 R74 = CMP-0094624-1: 4.7 kOhms ±5% 0.1W, 1/10W Chip Resistor 0402 (1005 Metric) Automotive AEC-Q200 Thick Film; Manufacturer: Panasonic; AEC Grade: Grade 0; VDC_V: 50V; Power_W: 100mW; AEC Qualified: Yes; TempCo: 200ppm/°C; Value: 4.7k; SizeZ_mm: 0.4mm
R73 R75 = CMP-0026936-3: RES, 47, 5%, 0.063 W, AEC-Q200 Grade 0, 0402; Manufacturer: Vishay-Dale; Power_W: 63mW; TempCo: 200 ppm/C; Value_Code: 47R0; Value: 47; EIA_Code: E24; SizeX_mm: 1; SizeY_mm: 0.5; SizeZ_mm: 0.6; Value2: 0.063W; AEC Qualified: Y; VDC_V: 50V; AEC Category: Q200; AEC Grade: 0
TP1 = CMP-0003968-1: Test Point, SMT; Manufacturer: Harwin
U1 = CMP-0076397-2: Zero Iq Reverse Polarity Protection Smart Diode Controller, DGK0008A (VSSOP-8); Manufacturer: Texas Instruments; SizeAreaWB_mm2: 23.6; SizeArea_mm2: 14.7; SizeZ_mm: 1.1; Green_REACh: Passed; SizeY_mm: 3; Green_Lifecycle: Active; CompType: IC; SizeX_mm: 4.9; AEC Category: Q200; AEC Qualified: Y
U2 U3 = CMP-0120692-1: 100-V, 53-A GaN Half-Bridge Power Stage; Manufacturer: Texas Instruments; SizeZ_mm: 0.85mm; AEC Qualified: No; Max Supply Voltage: 5.25V; Min Supply Voltage: 4.75V; Nominal Supply Current: 12mA; Number Of Outputs: 1; Standoff Height: 0mm; TJmax_C: +125°C

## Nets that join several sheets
GND: TIDA-010949 Power Optimizer_Aux (26 pins), TIDA-010949 Power Optimizer_MCU (13 pins), TIDA-010949 Power Optimizer_PLC (44 pins), TIDA-010949 Power Optimizer_Wireless (5 pins), TIDA-010949 Power Optimizer_Sampling (26 pins), TIDA-010949 Power Optimizer_power stage (26 pins)
PGND: TIDA-010949 Power Optimizer_PLC (C69.1 C84.1 L4.1 R23.2), TIDA-010949 Power Optimizer_Sampling (R34.1), TIDA-010949 Power Optimizer_power stage (39 pins)
PV_PGND: TIDA-010949 Power Optimizer_Top View (J1.2), TIDA-010949 Power Optimizer_Sampling (R37.1), TIDA-010949 Power Optimizer_power stage (R2.1)
String_PGND: TIDA-010949 Power Optimizer_Top View (J3.2), TIDA-010949 Power Optimizer_PLC (C69.2 L4.2 R23.1 T2.7)
Vafe: TIDA-010949 Power Optimizer_Aux (10 pins), TIDA-010949 Power Optimizer_PLC (10 pins)
VCC-3V3: TIDA-010949 Power Optimizer_Aux (6 pins), TIDA-010949 Power Optimizer_MCU (R29.2 R76.2), TIDA-010949 Power Optimizer_PLC (16 pins), TIDA-010949 Power Optimizer_Wireless (C57.2 C58.2 C59.2 J4.7), TIDA-010949 Power Optimizer_Sampling (5 pins), TIDA-010949 Power Optimizer_power stage (R72.2 R74.2)
VCC_5V: TIDA-010949 Power Optimizer_Aux (7 pins), TIDA-010949 Power Optimizer_MCU (J2.48 J2.84 J2.98 J2.112), TIDA-010949 Power Optimizer_power stage (10 pins)
VOUT: TIDA-010949 Power Optimizer_Top View (J3.1), TIDA-010949 Power Optimizer_Sampling (R41.2), TIDA-010949 Power Optimizer_power stage (22 pins)
ADCIN: TIDA-010949 Power Optimizer_MCU (J2.23), TIDA-010949 Power Optimizer_PLC (R57.2 TP27.1)
amb_tmp_mcu: TIDA-010949 Power Optimizer_MCU (J2.20), TIDA-010949 Power Optimizer_Sampling (C108.1 R63.1)
BOOST_FLT: TIDA-010949 Power Optimizer_MCU (J2.72), TIDA-010949 Power Optimizer_power stage (C109.2 R73.1)
BOOST_HI_PWM: TIDA-010949 Power Optimizer_MCU (J2.53), TIDA-010949 Power Optimizer_power stage (R10.1)
BOOST_LO_PWM: TIDA-010949 Power Optimizer_MCU (J2.55), TIDA-010949 Power Optimizer_power stage (R12.1)
BUCK_FLT: TIDA-010949 Power Optimizer_MCU (J2.54), TIDA-010949 Power Optimizer_power stage (C110.2 R75.1)
BUCK_HI_PWM: TIDA-010949 Power Optimizer_MCU (J2.50), TIDA-010949 Power Optimizer_power stage (R11.1)
BUCK_LO_PWM: TIDA-010949 Power Optimizer_MCU (J2.52), TIDA-010949 Power Optimizer_power stage (R13.1)
DAC_EN: TIDA-010949 Power Optimizer_MCU (J2.75), TIDA-010949 Power Optimizer_PLC (R53.2 U11.7)
Input_I: TIDA-010949 Power Optimizer_MCU (J2.14), TIDA-010949 Power Optimizer_Sampling (C72.1 R32.2 TP17.1)
Input_V: TIDA-010949 Power Optimizer_MCU (J2.12), TIDA-010949 Power Optimizer_Sampling (C74.1 R42.2)
INT: TIDA-010949 Power Optimizer_MCU (J2.85), TIDA-010949 Power Optimizer_PLC (R55.2 U11.9)
ISO1_5V: TIDA-010949 Power Optimizer_Aux (C44.2 D2.1 D4.1 R16.2), TIDA-010949 Power Optimizer_power stage (C31.1 C79.1 R3.1)
ISO1_GND: TIDA-010949 Power Optimizer_Aux (C44.1 D2.2 R16.1 T1.5), TIDA-010949 Power Optimizer_power stage (5 pins)
ISO2_5V: TIDA-010949 Power Optimizer_Aux (C45.2 D1.1 D3.1 R17.2), TIDA-010949 Power Optimizer_power stage (C30.1 C78.1 R4.1)
ISO2_GND: TIDA-010949 Power Optimizer_Aux (C45.1 D3.2 R17.1 T1.7), TIDA-010949 Power Optimizer_power stage (5 pins)
LED1_EN: TIDA-010949 Power Optimizer_MCU (J2.68), TIDA-010949 Power Optimizer_PLC (D15.1)
LED2_EN: TIDA-010949 Power Optimizer_MCU (J2.70), TIDA-010949 Power Optimizer_PLC (D16.1)
Output_I: TIDA-010949 Power Optimizer_MCU (J2.24), TIDA-010949 Power Optimizer_Sampling (C70.1 R31.2 TP16.1)
Output_V: TIDA-010949 Power Optimizer_MCU (J2.26), TIDA-010949 Power Optimizer_Sampling (C76.1 R44.2)
PGOOD_5V: TIDA-010949 Power Optimizer_Aux (C112.1 R19.2), TIDA-010949 Power Optimizer_MCU (J2.56)
PLC_HRPWM1: TIDA-010949 Power Optimizer_MCU (J2.49), TIDA-010949 Power Optimizer_PLC (R30.2 TP22.1)
PLC_HRPWM2: TIDA-010949 Power Optimizer_MCU (J2.51), TIDA-010949 Power Optimizer_PLC (R38.2 TP23.1)
RSD_MCU: TIDA-010949 Power Optimizer_MCU (J2.59), TIDA-010949 Power Optimizer_Wireless (J5.7)
RST_MCU: TIDA-010949 Power Optimizer_MCU (J2.57), TIDA-010949 Power Optimizer_Wireless (J4.2)
SD_EN: TIDA-010949 Power Optimizer_MCU (J2.77), TIDA-010949 Power Optimizer_PLC (R54.2 U11.8)
SPI_CLK: TIDA-010949 Power Optimizer_MCU (R27.1), TIDA-010949 Power Optimizer_PLC (R46.1 U11.3)
SPI_CS: TIDA-010949 Power Optimizer_MCU (R28.1), TIDA-010949 Power Optimizer_PLC (R49.1 U11.6)
SPI_SIMO: TIDA-010949 Power Optimizer_MCU (R24.1), TIDA-010949 Power Optimizer_PLC (R47.1 U11.4)
SPI_SOMI: TIDA-010949 Power Optimizer_MCU (R26.1), TIDA-010949 Power Optimizer_PLC (R48.1 U11.5)
SW1: TIDA-010949 Power Optimizer_Sampling (U7.1), TIDA-010949 Power Optimizer_power stage (U3.5)
SW2: TIDA-010949 Power Optimizer_Sampling (U7.2), TIDA-010949 Power Optimizer_power stage (L1.1)
UART_RX: TIDA-010949 Power Optimizer_MCU (J2.76), TIDA-010949 Power Optimizer_Wireless (J5.5)
UART_TX: TIDA-010949 Power Optimizer_MCU (J2.78), TIDA-010949 Power Optimizer_Wireless (J5.6)
VIN+: TIDA-010949 Power Optimizer_Top View (J1.1), TIDA-010949 Power Optimizer_Aux (5 pins), TIDA-010949 Power Optimizer_Sampling (R40.2), TIDA-010949 Power Optimizer_power stage (17 pins)

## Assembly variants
001: not fitted FID1 FID2 FID3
